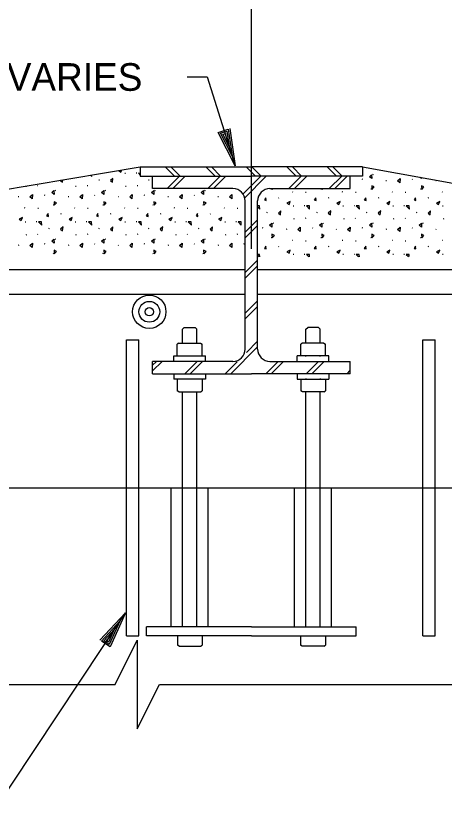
# Model space of a CAD drawing. Extents: x 0 to 320, y -4 to 473.
# Drawn here: x 10.256 to 12.428, y 2.526 to 6.592 of the extents above; entities that cross this region are included whole.
import ezdxf

# ---------------------------------------------------------------- set-up
doc = ezdxf.new("R2010")
doc.units = 0
for name, color, linetype in [('Level 2', 7, 'Continuous'), ('Level 3', 7, 'Continuous'), ('Level 44', 7, 'Continuous'), ('Level 50', 7, 'Continuous')]:
    doc.layers.add(name, color=color, linetype=linetype)

msp = doc.modelspace()

# ---------------------------------------------------------------- linework, layer by layer
at = {"layer": 'Level 2'}
for p, q in [((10.1354, 5.7025), (10.8854, 5.8276)), ((10.8854, 5.8276), (10.8854, 5.7807)), ((10.8854, 5.8276), (11.4479, 5.8276)), ((11.0586, 5.7807), (11.0118, 5.8276)), ((11.0869, 5.7807), (11.0401, 5.8276)), ((11.2637, 5.7807), (11.2168, 5.8276)), ((11.292, 5.7807), (11.2451, 5.8276)), ((11.4688, 5.7807), (11.4219, 5.8276)), ((12.0104, 5.8276), (11.4479, 5.8276)), ((11.4971, 5.7807), (11.4502, 5.8276)), ((11.6738, 5.7807), (11.627, 5.8276)), ((11.7021, 5.7807), (11.6552, 5.8276)), ((11.8789, 5.7807), (11.832, 5.8276)), ((11.9072, 5.7807), (11.8603, 5.8276)), ((12.0104, 5.8276), (12.0104, 5.7807)), ((12.0104, 5.8276), (12.7057, 5.7025)), ((10.8854, 5.7807), (11.4479, 5.7807)), ((10.9479, 5.7182), (10.9479, 5.7807)), ((11.0221, 5.7182), (11.0846, 5.7807)), ((11.0504, 5.7182), (11.1129, 5.7807)), ((11.2272, 5.7182), (11.2897, 5.7807)), ((11.2555, 5.7182), (11.318, 5.7807)), ((11.4054, 5.6913), (11.4948, 5.7807)), ((11.4144, 5.672), (11.5231, 5.7807)), ((12.0104, 5.7807), (11.4479, 5.7807)), ((11.6373, 5.7182), (11.6998, 5.7807)), ((11.6656, 5.7182), (11.7281, 5.7807)), ((11.8424, 5.7182), (11.9049, 5.7807)), ((11.8707, 5.7182), (11.9332, 5.7807)), ((11.9479, 5.7182), (11.9479, 5.7807)), ((11.3541, 5.7182), (10.9479, 5.7182)), ((11.5416, 5.7182), (11.9479, 5.7182)), ((11.4166, 4.9057), (11.4166, 5.6557)), ((11.4791, 4.9057), (11.4791, 5.6557)), ((11.4166, 5.4975), (11.4791, 5.56)), ((11.4166, 5.4692), (11.4791, 5.5317)), ((11.4166, 5.2924), (11.4791, 5.3549)), ((11.4166, 5.3068), (9.8385, 5.3068)), ((11.4166, 5.2641), (11.4791, 5.3266)), ((13.0026, 5.3068), (11.4791, 5.3068)), ((11.4166, 5.1818), (9.8385, 5.1818)), ((13.0026, 5.1818), (11.4791, 5.1818)), ((11.4166, 5.0873), (11.4791, 5.1498)), ((11.4166, 5.059), (11.4791, 5.1215)), ((11.099, 5.006), (11.1081, 5.015)), ((11.099, 4.9349), (11.099, 5.006)), ((11.1081, 5.015), (11.1626, 5.015)), ((11.1717, 5.006), (11.1626, 5.015)), ((11.1717, 4.9349), (11.1717, 5.006)), ((11.724, 5.006), (11.7331, 5.015)), ((11.724, 4.9349), (11.724, 5.006)), ((11.7876, 5.015), (11.7331, 5.015)), ((11.7967, 5.006), (11.7876, 5.015)), ((11.7967, 4.9349), (11.7967, 5.006)), ((10.8151, 3.4525), (10.8151, 4.9525)), ((10.8776, 3.4525), (10.8776, 4.9525)), ((11.081, 4.9349), (11.0726, 4.93)), ((11.0726, 4.8704), (11.0726, 4.93)), ((11.081, 4.9349), (11.1897, 4.9349)), ((11.1897, 4.9349), (11.1981, 4.93)), ((11.1981, 4.8704), (11.1981, 4.93)), ((11.4791, 4.9448), (11.4229, 4.8886)), ((11.706, 4.9349), (11.6976, 4.93)), ((11.6976, 4.8704), (11.6976, 4.93)), ((11.8147, 4.9349), (11.706, 4.9349)), ((11.8147, 4.9349), (11.8231, 4.93)), ((11.8231, 4.8704), (11.8231, 4.93)), ((12.3151, 3.4525), (12.3151, 4.9525)), ((12.3776, 3.4525), (12.3776, 4.9525)), ((11.3433, 4.7807), (11.4791, 4.9165)), ((11.3541, 4.8432), (10.9479, 4.8432)), ((10.9479, 4.7807), (10.9479, 4.8432)), ((10.9479, 4.7954), (10.9957, 4.8432)), ((10.9479, 4.8236), (10.9674, 4.8432)), ((11.0551, 4.8704), (11.2156, 4.8704)), ((11.0551, 4.8432), (11.0551, 4.8704)), ((11.099, 4.8681), (11.099, 4.8704)), ((11.11, 4.7807), (11.1725, 4.8432)), ((11.1382, 4.7807), (11.2007, 4.8432)), ((11.1717, 4.8681), (11.1717, 4.8704)), ((11.2156, 4.8432), (11.2156, 4.8704)), ((11.315, 4.7807), (11.3754, 4.8411)), ((11.5201, 4.7807), (11.5826, 4.8432)), ((11.5416, 4.8432), (11.9479, 4.8432)), ((11.5484, 4.7807), (11.6109, 4.8432)), ((11.8406, 4.8704), (11.6801, 4.8704)), ((11.6801, 4.8432), (11.6801, 4.8704)), ((11.724, 4.8681), (11.724, 4.8704)), ((11.7251, 4.7807), (11.7876, 4.8432)), ((11.7534, 4.7807), (11.8159, 4.8432)), ((11.7967, 4.8681), (11.7967, 4.8704)), ((11.8406, 4.8432), (11.8406, 4.8704)), ((11.9479, 4.7807), (11.9479, 4.8432)), ((11.9302, 4.7807), (11.9479, 4.7983)), ((10.9479, 4.7807), (11.4479, 4.7807)), ((11.0551, 4.7807), (11.0551, 4.7532)), ((11.2156, 4.7807), (11.2156, 4.7532)), ((11.9479, 4.7807), (11.4479, 4.7807)), ((11.6801, 4.7807), (11.6801, 4.7532)), ((11.8406, 4.7807), (11.8406, 4.7532)), ((11.2156, 4.7532), (11.0551, 4.7532)), ((11.0726, 4.7532), (11.0726, 4.6936)), ((11.099, 4.7555), (11.099, 4.7532)), ((11.1717, 4.7555), (11.1717, 4.7532)), ((11.1981, 4.7532), (11.1981, 4.6936)), ((11.6801, 4.7532), (11.8406, 4.7532)), ((11.6976, 4.7532), (11.6976, 4.6936)), ((11.724, 4.7555), (11.724, 4.7532)), ((11.7967, 4.7555), (11.7967, 4.7532)), ((11.8231, 4.7532), (11.8231, 4.6936)), ((11.081, 4.6887), (11.0726, 4.6936)), ((11.081, 4.6887), (11.1897, 4.6887)), ((11.099, 3.4994), (11.099, 4.6887)), ((11.1717, 3.4994), (11.1717, 4.6887)), ((11.1897, 4.6887), (11.1981, 4.6936)), ((11.706, 4.6887), (11.6976, 4.6936)), ((11.8147, 4.6887), (11.706, 4.6887)), ((11.724, 3.4994), (11.724, 4.6887)), ((11.7967, 3.4994), (11.7967, 4.6887)), ((11.8147, 4.6887), (11.8231, 4.6936)), ((7.5674, 4.2025), (14.9124, 4.2025)), ((11.0416, 3.4994), (11.0416, 4.2026)), ((11.2291, 3.4994), (11.2291, 4.2026)), ((11.6666, 3.4994), (11.6666, 4.2026)), ((11.8541, 3.4994), (11.8541, 4.2026)), ((11.4479, 3.4994), (10.9166, 3.4994)), ((10.9166, 3.4526), (10.9166, 3.4994)), ((11.4479, 3.4994), (11.9791, 3.4994)), ((11.9791, 3.4526), (11.9791, 3.4994)), ((11.4479, 3.4526), (10.9166, 3.4526)), ((11.1047, 3.4523), (11.0729, 3.4523)), ((11.0729, 3.4523), (11.0729, 3.4063)), ((11.0993, 3.4546), (11.0993, 3.4523)), ((11.1721, 3.4546), (11.1721, 3.4523)), ((11.1985, 3.4523), (11.1985, 3.4063)), ((11.4479, 3.4526), (11.9791, 3.4526)), ((11.6972, 3.4523), (11.6972, 3.4063)), ((11.7236, 3.4546), (11.7236, 3.4523)), ((11.791, 3.4523), (11.8228, 3.4523)), ((11.7964, 3.4546), (11.7964, 3.4523)), ((11.8228, 3.4523), (11.8228, 3.4063)), ((11.0813, 3.4014), (11.0729, 3.4063)), ((11.0813, 3.4014), (11.1901, 3.4014)), ((11.1901, 3.4014), (11.1985, 3.4063)), ((11.7056, 3.4014), (11.6972, 3.4063)), ((11.8144, 3.4014), (11.7056, 3.4014)), ((11.8144, 3.4014), (11.8228, 3.4063))]:
    msp.add_line(p, q, dxfattribs=at)
for centre, start, end in [((11.3541, 5.6557), 0, 90), ((11.5416, 5.6557), 90, 180), ((11.3541, 4.9057), 270, 0), ((11.5416, 4.9057), 180, 270)]:
    msp.add_arc(centre, 0.0625, start, end, dxfattribs=at)
at = {"layer": 'Level 3'}
for p, q in [((11.3501, 5.8835), (11.3501, 5.8835)), ((11.3658, 5.834), (11.3658, 5.834)), ((10.8098, 3.5702), (10.8098, 3.5702)), ((10.781, 3.5268), (10.781, 3.5268))]:
    msp.add_line(p, q, dxfattribs=at)
for points in [[(11.1234, 6.2833), (11.2232, 6.2833), (11.3658, 5.834)], [(11.3388, 6.0216), (11.3658, 5.834), (11.2797, 6.0028), (11.3302, 6.0189), (11.3501, 5.8835), (11.2917, 5.9982), (11.3241, 6.0085), (11.335, 5.9312), (11.3036, 5.9936), (11.3169, 5.9979), (11.3192, 5.9807)], [(9.9929, 2.5257), (10.1174, 2.5257), (10.8098, 3.5702)], [(10.6806, 3.4314), (10.8098, 3.5702), (10.7323, 3.3972), (10.6881, 3.4265), (10.781, 3.5268), (10.7284, 3.4094), (10.7, 3.4282), (10.7534, 3.4852), (10.7244, 3.4216), (10.7128, 3.4293), (10.7247, 3.4418)]]:
    msp.add_lwpolyline(points, dxfattribs=at)
at = {"layer": 'Level 44'}
for p, q in [((10.811, 5.7947), (10.8077, 5.7947)), ((10.867, 5.7959), (10.8638, 5.7959)), ((12.066, 5.787), (12.0632, 5.7887)), ((10.6782, 5.7609), (10.6749, 5.7615)), ((10.9307, 5.7609), (10.9274, 5.7615)), ((12.0116, 5.7637), (12.0089, 5.765)), ((12.1315, 5.7577), (12.1287, 5.7575)), ((12.2641, 5.7637), (12.2614, 5.765)), ((12.384, 5.7577), (12.3812, 5.7575)), ((10.3087, 5.7293), (10.3053, 5.7283)), ((10.367, 5.7326), (10.3645, 5.7317)), ((10.4575, 5.7061), (10.4547, 5.7078)), ((10.5612, 5.7293), (10.5578, 5.7283)), ((10.6195, 5.7326), (10.617, 5.7317)), ((10.71, 5.7061), (10.7072, 5.7078)), ((10.8137, 5.7293), (10.8103, 5.7283)), ((10.872, 5.7326), (10.8695, 5.7317)), ((10.9625, 5.7061), (10.9597, 5.7078)), ((11.215, 5.7061), (11.2122, 5.7078)), ((11.5497, 5.7152), (11.5472, 5.7154)), ((11.6581, 5.7005), (11.6556, 5.701)), ((11.7253, 5.6984), (11.7219, 5.6984)), ((11.8022, 5.7152), (11.7997, 5.7154)), ((11.9106, 5.7005), (11.9081, 5.701)), ((11.9778, 5.6984), (11.9744, 5.6984)), ((12.0547, 5.7152), (12.0522, 5.7154)), ((12.1631, 5.7005), (12.1606, 5.701)), ((12.2303, 5.6984), (12.2269, 5.6984)), ((12.3072, 5.7152), (12.3047, 5.7154)), ((12.4156, 5.7005), (12.4131, 5.701)), ((10.2705, 5.6769), (10.2677, 5.6766)), ((10.403, 5.6829), (10.4003, 5.6841)), ((10.523, 5.6769), (10.5202, 5.6766)), ((10.6555, 5.6829), (10.6528, 5.6841)), ((10.7755, 5.6769), (10.7727, 5.6766)), ((10.908, 5.6829), (10.9053, 5.6841)), ((11.028, 5.6769), (11.0252, 5.6766)), ((11.1605, 5.6829), (11.1578, 5.6841)), ((11.2805, 5.6769), (11.2777, 5.6766)), ((11.5873, 5.6711), (11.5843, 5.6696)), ((11.8398, 5.6711), (11.8368, 5.6696)), ((12.0923, 5.6711), (12.0893, 5.6696)), ((12.3448, 5.6711), (12.3418, 5.6696)), ((10.302, 5.6197), (10.2995, 5.6201)), ((10.3693, 5.6176), (10.3659, 5.6176)), ((10.4462, 5.6343), (10.4437, 5.6345)), ((10.5545, 5.6197), (10.552, 5.6201)), ((10.6218, 5.6176), (10.6184, 5.6176)), ((10.6987, 5.6343), (10.6962, 5.6345)), ((10.807, 5.6197), (10.8045, 5.6201)), ((10.8743, 5.6176), (10.8709, 5.6176)), ((10.9512, 5.6343), (10.9487, 5.6345)), ((11.0595, 5.6197), (11.057, 5.6201)), ((11.1268, 5.6176), (11.1234, 5.6176)), ((11.2037, 5.6343), (11.2012, 5.6345)), ((11.312, 5.6197), (11.3095, 5.6201)), ((11.3793, 5.6176), (11.3759, 5.6176)), ((11.6621, 5.6296), (11.6587, 5.6296)), ((11.7181, 5.6308), (11.7149, 5.6308)), ((11.9146, 5.6296), (11.9112, 5.6296)), ((11.9706, 5.6308), (11.9674, 5.6308)), ((12.1671, 5.6296), (12.1637, 5.6296)), ((12.2231, 5.6308), (12.2199, 5.6308)), ((12.4196, 5.6296), (12.4162, 5.6296)), ((10.4838, 5.5903), (10.4808, 5.5888)), ((10.7363, 5.5903), (10.7333, 5.5888)), ((10.9888, 5.5903), (10.9858, 5.5888)), ((11.2413, 5.5903), (11.2383, 5.5888)), ((11.5292, 5.5959), (11.5259, 5.5964)), ((11.7817, 5.5959), (11.7784, 5.5964)), ((12.0342, 5.5959), (12.0309, 5.5964)), ((12.2867, 5.5959), (12.2834, 5.5964)), ((10.306, 5.5488), (10.3027, 5.5488)), ((10.362, 5.5499), (10.3588, 5.5499)), ((10.5585, 5.5488), (10.5552, 5.5488)), ((10.6145, 5.5499), (10.6113, 5.5499)), ((10.811, 5.5488), (10.8077, 5.5488)), ((10.867, 5.5499), (10.8638, 5.5499)), ((11.0635, 5.5488), (11.0602, 5.5488)), ((11.1195, 5.5499), (11.1163, 5.5499)), ((11.316, 5.5488), (11.3127, 5.5488)), ((11.372, 5.5499), (11.3688, 5.5499)), ((11.561, 5.541), (11.5582, 5.5427)), ((11.6647, 5.5642), (11.6614, 5.5632)), ((11.723, 5.5675), (11.7206, 5.5666)), ((11.8135, 5.541), (11.8107, 5.5427)), ((11.9172, 5.5642), (11.9139, 5.5632)), ((11.9755, 5.5675), (11.9731, 5.5666)), ((12.066, 5.541), (12.0632, 5.5427)), ((12.1697, 5.5642), (12.1664, 5.5632)), ((12.228, 5.5675), (12.2256, 5.5666)), ((12.3185, 5.541), (12.3157, 5.5427)), ((12.4222, 5.5642), (12.4189, 5.5632)), ((10.4257, 5.515), (10.4224, 5.5156)), ((10.6782, 5.515), (10.6749, 5.5156)), ((10.9307, 5.515), (10.9274, 5.5156)), ((11.1832, 5.515), (11.1799, 5.5156)), ((11.5066, 5.5178), (11.5039, 5.519)), ((11.6265, 5.5118), (11.6237, 5.5115)), ((11.7591, 5.5178), (11.7564, 5.519)), ((11.879, 5.5118), (11.8762, 5.5115)), ((12.0116, 5.5178), (12.0089, 5.519)), ((12.1315, 5.5118), (12.1287, 5.5115)), ((12.2641, 5.5178), (12.2614, 5.519)), ((12.384, 5.5118), (12.3812, 5.5115)), ((10.3087, 5.4833), (10.3053, 5.4824)), ((10.367, 5.4867), (10.3645, 5.4858)), ((10.4575, 5.4602), (10.4547, 5.4619)), ((10.5612, 5.4833), (10.5578, 5.4824)), ((10.6195, 5.4867), (10.617, 5.4858)), ((10.71, 5.4602), (10.7072, 5.4619)), ((10.8137, 5.4833), (10.8103, 5.4824)), ((10.872, 5.4867), (10.8695, 5.4858)), ((10.9625, 5.4602), (10.9597, 5.4619)), ((11.0662, 5.4833), (11.0628, 5.4824)), ((11.1245, 5.4867), (11.122, 5.4858)), ((11.215, 5.4602), (11.2122, 5.4619)), ((11.3187, 5.4833), (11.3153, 5.4824)), ((11.377, 5.4867), (11.3745, 5.4858)), ((11.5497, 5.4692), (11.5472, 5.4694)), ((11.6581, 5.4546), (11.6556, 5.455)), ((11.7253, 5.4525), (11.7219, 5.4525)), ((11.8022, 5.4692), (11.7997, 5.4694)), ((11.9106, 5.4546), (11.9081, 5.455)), ((11.9778, 5.4525), (11.9744, 5.4525)), ((12.0547, 5.4692), (12.0522, 5.4694)), ((12.1631, 5.4546), (12.1606, 5.455)), ((12.2303, 5.4525), (12.2269, 5.4525)), ((12.3072, 5.4692), (12.3047, 5.4694)), ((12.4156, 5.4546), (12.4131, 5.455)), ((10.2705, 5.4309), (10.2677, 5.4307)), ((10.403, 5.4369), (10.4003, 5.4382)), ((10.523, 5.4309), (10.5202, 5.4307)), ((10.6555, 5.4369), (10.6528, 5.4382)), ((10.7755, 5.4309), (10.7727, 5.4307)), ((10.908, 5.4369), (10.9053, 5.4382)), ((11.028, 5.4309), (11.0252, 5.4307)), ((11.1605, 5.4369), (11.1578, 5.4382)), ((11.2805, 5.4309), (11.2777, 5.4307)), ((11.413, 5.4369), (11.4103, 5.4382)), ((11.5873, 5.4252), (11.5843, 5.4237)), ((11.8398, 5.4252), (11.8368, 5.4237)), ((12.0923, 5.4252), (12.0893, 5.4237)), ((12.3448, 5.4252), (12.3418, 5.4237)), ((10.4462, 5.3884), (10.4437, 5.3886)), ((10.6987, 5.3884), (10.6962, 5.3886)), ((10.9512, 5.3884), (10.9487, 5.3886)), ((11.2037, 5.3884), (11.2012, 5.3886)), ((11.6621, 5.3837), (11.6587, 5.3837)), ((11.7181, 5.3849), (11.7149, 5.3849)), ((11.9146, 5.3837), (11.9112, 5.3837)), ((11.9706, 5.3849), (11.9674, 5.3849)), ((12.1671, 5.3837), (12.1637, 5.3837)), ((12.2231, 5.3849), (12.2199, 5.3849)), ((12.4196, 5.3837), (12.4162, 5.3837)), ((10.8151, 4.9525), (10.8776, 4.9525)), ((12.3151, 4.9525), (12.3776, 4.9525)), ((10.8151, 3.4525), (10.8776, 3.4525)), ((12.3151, 3.4525), (12.3776, 3.4525)), ((9.0159, 3.2068), (10.7577, 3.2068)), ((10.9819, 3.2068), (12.9835, 3.2068))]:
    msp.add_line(p, q, dxfattribs=at)
for points in [[(10.6331, 5.7855), (10.6392, 5.7793), (10.6386, 5.7864)], [(10.7774, 5.8096), (10.7768, 5.8093), (10.7874, 5.802)], [(10.7874, 5.802), (10.7912, 5.8119)], [(10.8854, 5.7953), (10.8755, 5.7959), (10.8854, 5.7858)], [(10.8903, 5.7807), (10.8917, 5.7793), (10.8916, 5.7807)], [(12.3096, 5.7693), (12.3019, 5.7751)], [(10.4831, 5.7605), (10.4811, 5.7588), (10.4917, 5.7498), (10.4931, 5.7622)], [(12.3095, 5.7738), (12.3096, 5.7693)], [(11.5531, 5.7182), (11.5534, 5.7143)], [(11.5534, 5.7143), (11.5568, 5.7182)], [(11.8056, 5.7182), (11.8059, 5.7143)], [(11.8059, 5.7143), (11.8093, 5.7182)], [(11.489, 5.63), (11.4792, 5.6305)], [(11.4792, 5.6255), (11.4902, 5.6142), (11.489, 5.63)], [(11.489, 5.384), (11.4797, 5.3845)], [(11.4797, 5.379), (11.4866, 5.3719)], [(11.4899, 5.3719), (11.489, 5.384)], [(11.7415, 5.384), (11.7265, 5.3849), (11.7386, 5.3725)], [(11.7424, 5.3725), (11.7415, 5.384)], [(11.994, 5.384), (11.979, 5.3849), (11.9906, 5.373)], [(11.9949, 5.373), (11.994, 5.384)], [(12.2465, 5.384), (12.2315, 5.3849), (12.2425, 5.3736)], [(12.2473, 5.3736), (12.2465, 5.384)]]:
    msp.add_lwpolyline(points, dxfattribs=at)
for points in [[(12.0571, 5.7693), (12.0451, 5.7784), (12.0566, 5.7885)], [(10.7464, 5.7699), (10.7336, 5.7588), (10.7442, 5.7498)], [(12.1991, 5.7467), (12.1875, 5.7574), (12.2003, 5.7689)], [(10.4486, 5.6884), (10.4366, 5.6975), (10.4481, 5.7077)], [(10.7011, 5.6884), (10.6891, 5.6975), (10.7006, 5.7077)], [(10.9536, 5.6884), (10.9416, 5.6975), (10.9531, 5.7077)], [(11.2061, 5.6884), (11.1941, 5.6975), (11.2056, 5.7077)], [(12.0584, 5.7143), (12.0691, 5.7263), (12.0571, 5.7327)], [(12.3109, 5.7143), (12.3216, 5.7263), (12.3096, 5.7327)], [(10.338, 5.6659), (10.3265, 5.6766), (10.3393, 5.688)], [(10.5905, 5.6659), (10.579, 5.6766), (10.5918, 5.688)], [(10.843, 5.6659), (10.8315, 5.6766), (10.8443, 5.688)], [(11.0955, 5.6659), (11.084, 5.6766), (11.0968, 5.688)], [(11.348, 5.6659), (11.3365, 5.6766), (11.3493, 5.688)], [(11.5233, 5.6584), (11.5216, 5.6721), (11.5139, 5.6607)], [(11.6384, 5.6369), (11.6444, 5.6522), (11.6278, 5.6442)], [(11.7758, 5.6584), (11.7741, 5.6721), (11.7664, 5.6607)], [(11.8909, 5.6369), (11.8969, 5.6522), (11.8803, 5.6442)], [(12.0283, 5.6584), (12.0266, 5.6721), (12.0189, 5.6607)], [(12.1434, 5.6369), (12.1494, 5.6522), (12.1328, 5.6442)], [(12.2808, 5.6584), (12.2791, 5.6721), (12.2714, 5.6607)], [(12.3959, 5.6369), (12.4019, 5.6522), (12.3853, 5.6442)], [(10.4498, 5.6334), (10.4605, 5.6454), (10.4486, 5.6518)], [(10.7023, 5.6334), (10.713, 5.6454), (10.7011, 5.6518)], [(10.9548, 5.6334), (10.9655, 5.6454), (10.9536, 5.6518)], [(11.2073, 5.6334), (11.218, 5.6454), (11.2061, 5.6518)], [(11.7415, 5.63), (11.7265, 5.6308), (11.7427, 5.6142)], [(11.994, 5.63), (11.979, 5.6308), (11.9952, 5.6142)], [(12.2465, 5.63), (12.2315, 5.6308), (12.2477, 5.6142)], [(10.2824, 5.5561), (10.2883, 5.5714), (10.2718, 5.5633)], [(10.4198, 5.5776), (10.418, 5.5913), (10.4103, 5.5798)], [(10.5349, 5.5561), (10.5408, 5.5714), (10.5243, 5.5633)], [(10.6723, 5.5776), (10.6705, 5.5913), (10.6628, 5.5798)], [(10.7874, 5.5561), (10.7933, 5.5714), (10.7768, 5.5633)], [(10.9248, 5.5776), (10.923, 5.5913), (10.9153, 5.5798)], [(11.0399, 5.5561), (11.0458, 5.5714), (11.0293, 5.5633)], [(11.1773, 5.5776), (11.1755, 5.5913), (11.1678, 5.5798)], [(11.2924, 5.5561), (11.2983, 5.5714), (11.2818, 5.5633)], [(11.5974, 5.6049), (11.5846, 5.5937), (11.5952, 5.5847)], [(11.8499, 5.6049), (11.8371, 5.5937), (11.8477, 5.5847)], [(12.1024, 5.6049), (12.0896, 5.5937), (12.1002, 5.5847)], [(12.3549, 5.6049), (12.3421, 5.5937), (12.3527, 5.5847)], [(10.3855, 5.5491), (10.3705, 5.5499), (10.3867, 5.5333)], [(10.638, 5.5491), (10.623, 5.5499), (10.6392, 5.5333)], [(10.8905, 5.5491), (10.8755, 5.5499), (10.8917, 5.5333)], [(11.143, 5.5491), (11.128, 5.5499), (11.1442, 5.5333)], [(11.3955, 5.5491), (11.3805, 5.5499), (11.3967, 5.5333)], [(11.5521, 5.5234), (11.5401, 5.5324), (11.5516, 5.5426)], [(11.8046, 5.5234), (11.7926, 5.5324), (11.8041, 5.5426)], [(12.0571, 5.5234), (12.0451, 5.5324), (12.0566, 5.5426)], [(12.3096, 5.5234), (12.2976, 5.5324), (12.3091, 5.5426)], [(10.4939, 5.524), (10.4811, 5.5128), (10.4917, 5.5039)], [(10.7464, 5.524), (10.7336, 5.5128), (10.7442, 5.5039)], [(10.9989, 5.524), (10.9861, 5.5128), (10.9967, 5.5039)], [(11.2514, 5.524), (11.2386, 5.5128), (11.2492, 5.5039)], [(11.6941, 5.5008), (11.6825, 5.5115), (11.6953, 5.5229)], [(11.9466, 5.5008), (11.935, 5.5115), (11.9478, 5.5229)], [(12.1991, 5.5008), (12.1875, 5.5115), (12.2003, 5.5229)], [(10.4486, 5.4425), (10.4366, 5.4516), (10.4481, 5.4618)], [(10.7011, 5.4425), (10.6891, 5.4516), (10.7006, 5.4618)], [(10.9536, 5.4425), (10.9416, 5.4516), (10.9531, 5.4618)], [(11.2061, 5.4425), (11.1941, 5.4516), (11.2056, 5.4618)], [(11.5534, 5.4684), (11.5641, 5.4804), (11.5521, 5.4867)], [(11.8059, 5.4684), (11.8166, 5.4804), (11.8046, 5.4867)], [(12.0584, 5.4684), (12.0691, 5.4804), (12.0571, 5.4867)], [(12.3109, 5.4684), (12.3216, 5.4804), (12.3096, 5.4867)], [(10.338, 5.4199), (10.3265, 5.4306), (10.3393, 5.4421)], [(10.5905, 5.4199), (10.579, 5.4306), (10.5918, 5.4421)], [(10.843, 5.4199), (10.8315, 5.4306), (10.8443, 5.4421)], [(11.0955, 5.4199), (11.084, 5.4306), (11.0968, 5.4421)], [(11.348, 5.4199), (11.3365, 5.4306), (11.3493, 5.4421)], [(11.5233, 5.4125), (11.5216, 5.4262), (11.5139, 5.4147)], [(11.7758, 5.4125), (11.7741, 5.4262), (11.7664, 5.4147)], [(12.0283, 5.4125), (12.0266, 5.4262), (12.0189, 5.4147)], [(12.2808, 5.4125), (12.2791, 5.4262), (12.2714, 5.4147)], [(10.4498, 5.3875), (10.4605, 5.3995), (10.4486, 5.4059)], [(10.7023, 5.3875), (10.713, 5.3995), (10.7011, 5.4059)], [(10.9548, 5.3875), (10.9655, 5.3995), (10.9536, 5.4059)], [(11.2073, 5.3875), (11.218, 5.3995), (11.2061, 5.4059)], [(11.6384, 5.391), (11.6444, 5.4063), (11.6278, 5.3982)], [(11.8909, 5.391), (11.8969, 5.4063), (11.8803, 5.3982)], [(12.1434, 5.391), (12.1494, 5.4063), (12.1328, 5.3982)], [(12.3959, 5.391), (12.4019, 5.4063), (12.3853, 5.3982)]]:
    msp.add_lwpolyline(points, close=True, dxfattribs=at)
at = {"layer": 'Level 50'}
for p, q in [((11.4479, 5.4131), (11.4479, 6.8111)), ((10.7577, 3.2068), (10.8694, 3.4318)), ((10.8694, 3.4318), (10.8694, 2.9823)), ((10.8694, 2.9823), (10.9819, 3.2068))]:
    msp.add_line(p, q, dxfattribs=at)
for radius in [0.0844, 0.0527, 0.0211]:
    msp.add_circle((10.931, 5.0943), radius, dxfattribs=at)

# ---------------------------------------------------------------- texts
msp.add_text('EL. VARIES', height=0.14002, dxfattribs=at).set_placement((9.8759, 6.2133))

doc.saveas('drawing.dxf')
